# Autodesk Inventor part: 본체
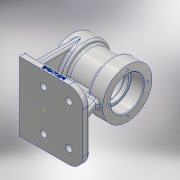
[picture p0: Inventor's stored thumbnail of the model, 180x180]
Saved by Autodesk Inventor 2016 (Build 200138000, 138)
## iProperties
Created: 2020-06
Part Number: 본체
Material: 알루미늄 6061
Document SubType Name: Modeling
Designer: woori
Density: 2.7 g/cm^3
Appearance: 알루미늄 - 평지
Mass: 725.092 g
Surface Area: 642.839 cm^2
Volume: 268.553 cm^3
Author: woori
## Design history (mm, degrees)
revolve "회전1" stored, may be unused: angle "d6" = 90 deg
sketch "스케치2"
  geometry: C1 r 23.5 at (0, 0); 1 further point
  constraints: 1 centre point, 1 coincident
  dimensions: "d7" = 47 diameter of C1
extrude "돌출1" cut sketch "스케치2" distance "d8" = 18; taper "d9" = 0 deg
sketch "스케치3"
  geometry: C1 r 20 at (0, 0); 1 further point
  constraints: 1 centre point, 1 coincident
  dimensions: "d10" = 40 diameter of C1
extrude "돌출2" cut sketch "스케치3" distance "d11" = 6; taper "d12" = 0 deg
sketch "스케치4"
  geometry: C1 r 23 at (0, 0); 1 further point
  constraints: 1 centre point, 1 coincident
  dimensions: "d13" = 46 diameter of C1
extrude "돌출3" cut sketch "스케치4" distance "d14" = 30; taper "d15" = 0 deg
sketch "스케치5"
  geometry: C1 r 20 at (0, 0); 1 further point
  constraints: 1 centre point, 1 coincident
  dimensions: "d16" = 40 diameter of C1
extrude "돌출4" cut sketch "스케치5" distance "d17" = 6; taper "d18" = 0 deg
sketch "스케치6"
  geometry: 1 further point
sketch "스케치7"
  geometry: C1 r 23.5 at (0, 0); 1 further point
  constraints: 1 centre point, 1 coincident
  dimensions: "d19" = 47 diameter of C1
extrude "돌출5" cut sketch "스케치7" distance "d20" = 18; taper "d21" = 0 deg
sketch "스케치8"
  geometry: A1 r 28.5 centre (0, 0) between (-28.5, 0) and (0, 28.5); 3 further points
  constraints: 4 point on circle, 1 centre point, 1 coincident
  dimensions: "d22" = 57 diameter of A1
hole "구멍1" sketch "스케치8" at (-28.5, 0), (0, 28.5), (0, -28.5), (28.5, 0) diameter "d23" = 3.242; stored, may be unused: countersink angle "d27" = 90 deg, drill point angle "d29" = 118 deg; dims "d24" = 10, "d25" = 4, "d26" = 2, "d28" = 12
chamfer "모따기1" distance "d30" = 1; stored, may be unused: second distance "d31" = 2, angle "d32" = 45 deg
chamfer "모따기2" distance "d33" = 1; stored, may be unused: second distance "d34" = 2, angle "d35" = 45 deg
fillet "모깎기1" dims "d36" = 0.3
fillet "모깎기2" dims "d37" = 3
fillet "모깎기3" dims "d38" = 3
node "작업 평면1"
sketch "스케치9"
  geometry: C1 r 6 at (0, 0); 1 further point
  constraints: 1 centre point, 1 coincident
  dimensions: "d40" = 12 diameter of C1
extrude "돌출6" join sketch "스케치9" stored distance "d41" = 18; taper "d42" = 0 deg
sketch "스케치10"
  geometry: 2 further points
  constraints: 1 coincident
hole "구멍2" sketch "스케치10" at (0, 0) diameter "d43" = 5.188; stored, may be unused: countersink angle "d47" = 90 deg, drill point angle "d49" = 118 deg; dims "d44" = 19, "d45" = 4, "d46" = 2, "d48" = 20
fillet "모깎기4" dims "d50" = 3
node "작업 평면2"
sketch "스케치11"
  geometry: L1 (39, 1.621)-(39, -1.621) reference; L2 (39, 0)-(34, 0); L3 (34, 0)-(-11, 0); L4 (34, 49)-(-56, 49); L5 (-56, 49)-(-56, -49); L6 (-56, -49)-(34, -49); L7 (34, -49)-(34, 49); L8 (34, 49)-(-56, -49); L9 (-56, 49)-(34, -49); 1 further point
  constraints: 16 end point, 3 midpoint, 2 horizontal, 2 parallel, 1 perpendicular, 1 point on line
  dimensions: "d52" = 5 distance of L2.start L2.end; "d53" = 45 distance of L2.end L3.end; "d54" = 90 distance of L6.end L5.end; "d55" = 98 distance of L5.end L4.end
extrude "돌출7" join sketch "스케치11" distance "d56" = 10; taper "d57" = 0 deg
sketch "스케치12"
  geometry: 1 further point
sketch "스케치13"
  geometry: L1 (-34, 49)-(-34, -49) reference; L2 (-34, 0)-(-29, 0); L3 (-34, -35)-(-24, -35); L4 (-24, -35)-(-24, 35); L5 (-24, 35)-(-34, 35); L6 (-34, 35)-(-34, -35); L7 (-34, -35)-(-24, 35); L8 (-24, -35)-(-34, 35); 1 further point
  constraints: 14 end point, 3 midpoint, 2 horizontal, 2 parallel, 1 perpendicular
  dimensions: "d63" = 5 distance of L2.start L2.end; "d64" = 10 distance of L5.end L4.end; "d65" = 70 distance of L4.end L3.end
extrude "돌출8" join sketch "스케치13" stored distance "d66" = 10; taper "d67" = 0 deg
sketch "스케치14"
  geometry: L1 (56, -80)-(56, -70) reference; L2 (56, -70)-(44, -70); L3 (56, -70)-(-34, -70) reference; L4 (44, -70)-(31.022, -34.342); L5 (44, -70)-(-24.231, -70); 1 further point
  constraints: 6 end point, 2 point on line
  dimensions: "d68" = 12 distance of L1.end L2.end; "d69" = 70 deg angle of L3 L4
feature "리브1" sketch "스케치14" dims "d70" = 1, "d71" = 10, "d72" = 0, "d73" = 0, "d74" = 1, "d75" = 1
sketch "스케치15"
  geometry: L1 (56, 49)-(-34, 49) reference; L2 (-34, 49)-(36, 49); L3 (36, 49)-(36, 29); L4 (36, 29)-(36, -29); L5 (36, -29)-(0, -29); L6 (0, -29)-(0, 29); C1 r 4.5 at (0, 29); C2 r 4.5 at (36, 29); C3 r 4.5 at (36, -29); C4 r 4.5 at (0, -29); 1 further point
  constraints: 10 end point, 4 centre point, 4 coincident, 3 vertical, 1 horizontal, 1 point on line
  dimensions: "d76" = 70 distance of L1.end L2.end; "d77" = 20 distance of L2.end L3.end; "d78" = 58 distance of L3.end L4.end; "d79" = 36 distance of L4.end L5.end; "d80" = 58 distance of L5.end L6.end; "d81" = 9 diameter of C1; "d82" = 9 diameter of C2; "d83" = 9 diameter of C3; "d84" = 9 diameter of C4
extrude "돌출9" cut sketch "스케치15" stored distance "d85" = 10; taper "d86" = 0 deg
sketch "스케치16"
  geometry: L1 (-34, 49)-(36, 49); L2 (56, 49)-(-34, 49) reference; L3 (56, -49)-(56, 49) reference; L4 (36, 49)-(56, 49); L5 (56, -29)-(56, -49); L6 (56, -49)-(36, -49); A1 r 20 centre (36, 29) between (56, 29) and (36, 49); A2 r 20 centre (36, -29) between (36, -49) and (56, -29); 1 further point
  constraints: 8 end point, 4 point on circle, 4 tangent, 3 point on line, 2 centre point, 2 collinear
  dimensions: "d87" = 70 distance of L1.start L1.end
extrude "돌출10" cut sketch "스케치16" stored distance "d90" = 10; taper "d91" = 0 deg
fillet "모깎기5" dims "d92" = 3
fillet "모깎기6" dims "d93" = 3
fillet "모깎기7" dims "d94" = 3
sketch "스케치17"
  geometry: L1 (0, 0)-(0, 7) reference; 2 further points
  constraints: 1 other
  dimensions: "d95" = 45 distance from line of L1 point (45, 4); "d96" = 4 vertical distance of point (45, 4) L1.start
feature "엠보싱1" sketch "스케치17" dims "d1" = 70, "d2" = 22, "d3" = 22, "d4" = 29, "d5" = 22, "d97" = 0.5, "d98" = 0
node "솔리드1"
mirror "대칭1"
sketch "스케치1"
  geometry: L1 (39, 0)-(39, 35); L2 (-39, 35)-(-39, 0); L3 (-39, -35)-(39, 35); L4 (39, -35)-(-39, 35); L5 (-39, 0)-(39, 0); L6 (-39, 35)-(-17, 35); L7 (-39, 0)-(-17, 0); L8 (39, 0)-(17, 0); L9 (17, 29)-(-17, 29); L10 (-17, 35)-(-17, 29); L11 (17, 29)-(17, 35); L12 (39, 35)-(17, 35); L13 (-17, 35)-(-39, 35); 1 further point
  constraints: 26 end point, 2 midpoint, 2 point on line, 1 parallel, 1 perpendicular
  dimensions: "d1" = 70 distance of L1.end L4.start; "d2" = 22 distance of L2.start L6.end; "d3" = 22 distance of L2.end L7.end; "d4" = 29 distance of L7.end L9.end; "d5" = 22 distance of L1.start L8.end
other parameters: "d39" = 32
